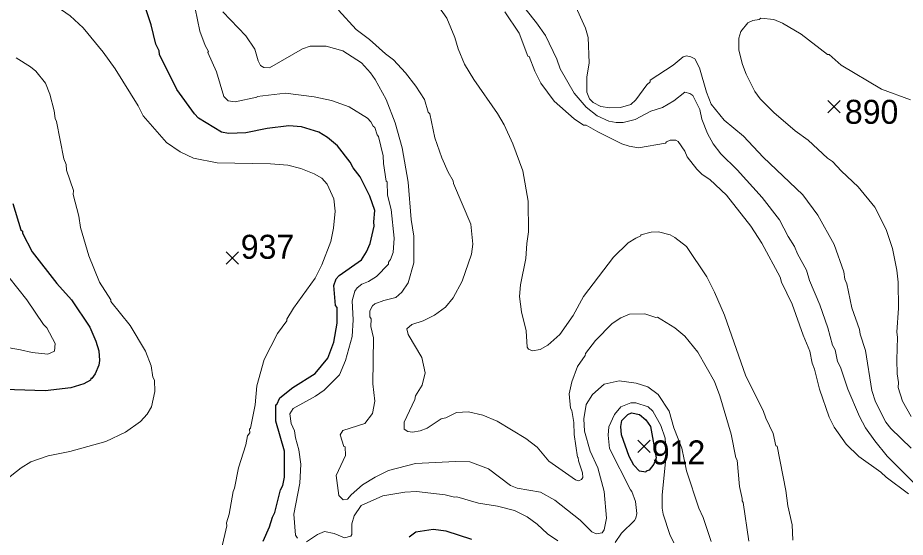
# Model space of a CAD drawing. Extents: x 265.7 to 292.1, y 7676.2 to 7704.2.
# Drawn here: x 279.917 to 282.881, y 7683.549 to 7685.284 of the extents above; entities that cross this region are included whole.
import ezdxf
from ezdxf.enums import TextEntityAlignment as Align

# ---------------------------------------------------------------- set-up
doc = ezdxf.new("R2010")
doc.units = 0
doc.header["$LTSCALE"] = 0.032
for name, color, linetype, lineweight in [('1', 7, 'Continuous', 25), ('2', 7, 'Continuous', 13), ('21', 7, 'Continuous', 25)]:
    doc.layers.add(name, color=color, linetype=linetype, lineweight=lineweight)
doc.layers.add('61', color=7, linetype='Continuous')

msp = doc.modelspace()

# ---------------------------------------------------------------- linework, layer by layer
at = {"layer": '1'}
for points in [[(280.4484, 7685.0448), (280.3902, 7685.1613), (280.3894, 7685.1741), (280.3782, 7685.1964), (280.3623, 7685.2603), (280.3431, 7685.3177), (280.3391, 7685.3497)], [(280.7365, 7683.5367), (280.758, 7683.5846), (280.7676, 7683.6165), (280.7756, 7683.6324), (280.7948, 7683.7074), (280.8019, 7683.7218), (280.8075, 7683.7505), (280.8075, 7683.8367), (280.7788, 7683.9373), (280.7788, 7683.9915), (280.782, 7683.9923), (280.7916, 7684.0155), (280.8355, 7684.049), (280.9097, 7684.0968), (280.9528, 7684.1471), (280.9719, 7684.2006), (280.9831, 7684.2644), (280.9831, 7684.3171), (280.9783, 7684.3235), (280.9719, 7684.3905), (280.9807, 7684.412), (280.9902, 7684.424), (281.0653, 7684.4759), (281.082, 7684.5022), (281.094, 7684.5309), (281.1076, 7684.5884), (281.106, 7684.6028), (281.1091, 7684.6403), (281.0932, 7684.6889), (281.0605, 7684.7528), (281.0373, 7684.7831), (281.027, 7684.8023), (280.9847, 7684.8565), (280.9512, 7684.8844), (280.9224, 7684.902), (280.865, 7684.9195), (280.8219, 7684.9235), (280.7501, 7684.9148), (280.6783, 7684.8996), (280.6208, 7684.898), (280.5977, 7684.902), (280.5211, 7684.9491), (280.5067, 7684.9634), (280.4484, 7685.0448)], [(279.901, 7684.6634), (279.9274, 7684.5756), (279.9329, 7684.5716), (279.9329, 7684.5652), (279.9649, 7684.5022), (280.0479, 7684.3969), (280.0965, 7684.3426), (280.1572, 7684.2509), (280.1779, 7684.2038), (280.1875, 7684.1719), (280.1899, 7684.1399), (280.1875, 7684.124), (280.1755, 7684.0953), (280.1644, 7684.0801), (280.1612, 7684.0801), (280.1596, 7684.0745), (280.1372, 7684.0617), (280.0942, 7684.0482), (280.008, 7684.0386), (279.7351, 7684.0474)], [(281.4331, 7683.5415), (281.347, 7683.5702), (281.3039, 7683.575), (281.2464, 7683.5662), (281.2241, 7683.5494)]]:
    msp.add_lwpolyline(points, dxfattribs=at)
msp.add_lwpolyline([(282.0299, 7683.9188), (282.0489, 7683.8144), (282.041, 7683.7938), (282.0252, 7683.7737), (282.0156, 7683.7705), (282.014, 7683.7665), (281.9933, 7683.7705), (281.9741, 7683.7904), (281.9582, 7683.8192), (281.9334, 7683.891), (281.931, 7683.9197), (281.9342, 7683.9397), (281.9542, 7683.9588), (281.9662, 7683.9652), (281.9933, 7683.9588), (282.014, 7683.9412)], close=True, dxfattribs=at)
at = {"layer": '2'}
for points in [[(280.2019, 7685.1693), (280.1356, 7685.2507), (280.0918, 7685.2906), (280.0167, 7685.3425), (279.9824, 7685.3616), (279.8931, 7685.4031), (279.7925, 7685.443)], [(281.5456, 7685.3983), (281.6494, 7685.2675), (281.6789, 7685.2252), (281.7172, 7685.1454), (281.7284, 7685.1135), (281.7747, 7685.0321), (281.8145, 7684.9858), (281.8513, 7684.9562), (281.8912, 7684.9387), (281.9151, 7684.9339), (281.939, 7684.9339), (281.9789, 7684.9443), (282.0308, 7684.9722), (282.0699, 7684.9842), (282.1082, 7685.0065), (282.1449, 7685.0352), (282.1609, 7685.0313), (282.1712, 7685.0241), (282.1944, 7684.9778), (282.2016, 7684.9459), (282.2199, 7684.898), (282.2391, 7684.8629), (282.2646, 7684.8302), (282.3197, 7684.7759), (282.4026, 7684.6842), (282.4601, 7684.6099), (282.4896, 7684.5533), (282.5112, 7684.5198), (282.5207, 7684.4958), (282.5511, 7684.4408), (282.5606, 7684.4065), (282.595, 7684.3259), (282.6221, 7684.2485), (282.638, 7684.191), (282.646, 7684.1751), (282.6548, 7684.1368), (282.6644, 7684.1176), (282.6891, 7684.0442), (282.7274, 7683.9532), (282.7482, 7683.9149), (282.7785, 7683.871), (282.82, 7683.82), (282.9086, 7683.7322)], [(281.7747, 7685.3329), (281.813, 7685.2499), (281.8217, 7685.2188), (281.8249, 7685.1342), (281.8177, 7685.0863), (281.8177, 7685.0353), (281.8265, 7685.0137), (281.8385, 7685.0009), (281.864, 7684.9882), (281.8944, 7684.9834), (281.9295, 7684.9842), (281.9638, 7684.9946), (281.9805, 7685.0097), (282.0172, 7685.06), (282.0284, 7685.0704), (282.0292, 7685.076), (282.105, 7685.1262), (282.1393, 7685.1533), (282.1505, 7685.1565), (282.1641, 7685.1541), (282.1776, 7685.147), (282.1936, 7685.1174), (282.2167, 7685.0353), (282.2327, 7684.9954), (282.2758, 7684.9419), (282.3404, 7684.8884), (282.4058, 7684.8182), (282.5383, 7684.6929), (282.5886, 7684.6251), (282.6436, 7684.527), (282.6756, 7684.4352), (282.6787, 7684.4113), (282.6859, 7684.3953), (282.7019, 7684.3155), (282.7274, 7684.2437), (282.7298, 7684.2277), (282.7474, 7684.1735), (282.7689, 7684.0394), (282.7809, 7684.0011), (282.8152, 7683.9341), (282.8327, 7683.9125), (282.8998, 7683.8471)], [(280.8514, 7683.5463), (280.845, 7683.5566), (280.8394, 7683.6261), (280.8586, 7683.7298), (280.8618, 7683.7936), (280.8554, 7683.8415), (280.8442, 7683.8814), (280.841, 7683.9053), (280.8299, 7683.9293), (280.8259, 7683.9612), (280.8371, 7683.9795), (280.9113, 7684.0202), (280.94, 7684.041), (280.9911, 7684.0913), (281.0118, 7684.1399), (281.0333, 7684.2197), (281.0373, 7684.2756), (281.0341, 7684.3394), (281.0421, 7684.3714), (281.0501, 7684.3825), (281.0661, 7684.3945), (281.0884, 7684.4033), (281.1147, 7684.42), (281.1554, 7684.4615), (281.1554, 7684.4679), (281.1618, 7684.4767), (281.1706, 7684.5006), (281.1738, 7684.5485), (281.1642, 7684.6443), (281.1522, 7684.6921), (281.1506, 7684.7368), (281.1475, 7684.7384), (281.1379, 7684.7975), (281.1371, 7684.823), (281.1219, 7684.8876), (281.1171, 7684.8932), (281.1092, 7684.918), (281.1036, 7684.9219), (281.0964, 7684.9371), (281.0852, 7684.9491), (281.0238, 7684.9866), (280.9647, 7685.0081), (280.9065, 7685.0201), (280.8107, 7685.0321), (280.7166, 7685.0217), (280.715, 7685.0185), (280.6432, 7685.0033), (280.6192, 7685.0065), (280.6048, 7685.0217), (280.5809, 7685.1039), (280.5522, 7685.1677), (280.5538, 7685.1717), (280.5426, 7685.1917), (280.525, 7685.2395), (280.5091, 7685.3153)], [(281.8154, 7683.9931), (281.8074, 7683.9452), (281.8098, 7683.9037), (281.8281, 7683.8367), (281.8544, 7683.7809), (281.8752, 7683.7027), (281.8832, 7683.6133), (281.8752, 7683.5742), (281.868, 7683.5638), (281.8481, 7683.5606), (281.8337, 7683.567), (281.7946, 7683.6061), (281.71, 7683.6731), (281.6629, 7683.6995), (281.5847, 7683.7138), (281.5624, 7683.7218), (281.489, 7683.7777), (281.4267, 7683.8008), (281.3789, 7683.8024), (281.2448, 7683.7952), (281.1554, 7683.7721), (281.1108, 7683.7505), (281.0677, 7683.7242), (281.0302, 7683.6915), (281.0182, 7683.6763), (281.0038, 7683.6747), (280.9887, 7683.6891), (280.9799, 7683.7553), (281.0118, 7683.8224), (281.0102, 7683.8511), (281.0062, 7683.8527), (280.9934, 7683.8918), (281.0022, 7683.9061), (281.0756, 7683.9293), (281.102, 7683.9628), (281.1092, 7684.0035), (281.1028, 7684.0617), (281.1044, 7684.215), (281.0964, 7684.2533), (281.0972, 7684.2788), (281.0932, 7684.2852), (281.0932, 7684.3051), (281.1012, 7684.3219), (281.1091, 7684.3291), (281.1395, 7684.3402), (281.1794, 7684.3498), (281.1993, 7684.3674), (281.2209, 7684.3985), (281.24, 7684.4655), (281.24, 7684.5549), (281.2304, 7684.6107), (281.2209, 7684.7352), (281.2009, 7684.8501), (281.1778, 7684.9331), (281.1475, 7685.0113), (281.1107, 7685.0783), (281.0948, 7685.1007), (281.0645, 7685.1334), (281.003, 7685.1741), (280.9464, 7685.1893), (280.8937, 7685.1893), (280.8682, 7685.1805), (280.7581, 7685.1166), (280.7389, 7685.1182), (280.7277, 7685.1246), (280.7198, 7685.1406), (280.7086, 7685.1789), (280.6783, 7685.2236), (280.6017, 7685.3034)], [(281.7675, 7683.9724), (281.7739, 7683.9325), (281.7755, 7683.8926), (281.7858, 7683.8168), (281.7882, 7683.816), (281.789, 7683.8048), (281.8026, 7683.7649), (281.8034, 7683.7489), (281.7994, 7683.7426), (281.789, 7683.7378), (281.7794, 7683.741), (281.6901, 7683.8032), (281.651, 7683.8503), (281.6135, 7683.879), (281.5177, 7683.9373), (281.4698, 7683.9572), (281.422, 7683.9684), (281.3821, 7683.966), (281.3469, 7683.9484), (281.331, 7683.9452), (281.2839, 7683.9141), (281.2608, 7683.9045), (281.2352, 7683.9005), (281.2201, 7683.9029), (281.2073, 7683.9109), (281.2073, 7683.9333), (281.2432, 7684.0091), (281.2456, 7684.0218), (281.2671, 7684.057), (281.2775, 7684.0985), (281.2664, 7684.1495), (281.2209, 7684.2261), (281.2161, 7684.2453), (281.2328, 7684.2604), (281.2703, 7684.2716), (281.3087, 7684.2915), (281.3454, 7684.3179), (281.3709, 7684.349), (281.4012, 7684.4049), (281.4323, 7684.4942), (281.4363, 7684.5278), (281.4299, 7684.5948), (281.3725, 7684.7304), (281.3709, 7684.74), (281.3541, 7684.7687), (281.3326, 7684.8166), (281.3102, 7684.8836), (281.2935, 7684.9634), (281.2879, 7684.969), (281.2751, 7685.0113), (281.2464, 7685.056), (281.2113, 7685.1007), (281.1722, 7685.1438), (281.1451, 7685.1637), (281.0916, 7685.2116), (281.0469, 7685.2451), (280.9879, 7685.309)], [(282.5056, 7683.5399), (282.5024, 7683.5909), (282.488, 7683.6548), (282.4816, 7683.7059), (282.4529, 7683.8535), (282.4489, 7683.8551), (282.4394, 7683.8958), (282.4146, 7683.9468), (282.4058, 7683.9724), (282.3484, 7684.0873), (282.2766, 7684.2916), (282.2439, 7684.3682), (282.2175, 7684.4192), (282.1497, 7684.5198), (282.1114, 7684.5509), (282.0954, 7684.5589), (282.0571, 7684.5692), (282.0316, 7684.5684), (281.9981, 7684.5589), (281.9981, 7684.5557), (281.9805, 7684.5485), (281.955, 7684.5325), (281.9063, 7684.4847), (281.8066, 7684.3538), (281.7715, 7684.29), (281.7268, 7684.2261), (281.6869, 7684.191), (281.6613, 7684.1766), (281.6358, 7684.1719), (281.623, 7684.1774), (281.6183, 7684.1838), (281.6151, 7684.2389), (281.5991, 7684.3027), (281.5927, 7684.3538), (281.5959, 7684.3921), (281.6135, 7684.4799), (281.6167, 7684.5309), (281.623, 7684.5692), (281.6214, 7684.6714), (281.6031, 7684.7735), (281.5704, 7684.8629), (281.5416, 7684.9267), (281.5193, 7684.965), (281.4403, 7685.0783), (281.4092, 7685.1294), (281.3876, 7685.1805), (281.3765, 7685.2188), (281.3493, 7685.2826), (281.323, 7685.3209)], [(281.544, 7685.3042), (281.5911, 7685.2332)], [(282.8982, 7685.0097), (282.8008, 7685.0456), (282.6668, 7685.1262), (282.6269, 7685.1613), (282.6205, 7685.1613), (282.5335, 7685.2292), (282.4705, 7685.2659), (282.4418, 7685.2778), (282.3987, 7685.2826), (282.3923, 7685.2786), (282.3715, 7685.2754), (282.3548, 7685.2667), (282.3316, 7685.2379), (282.3244, 7685.2156), (282.3252, 7685.1757), (282.3372, 7685.1278), (282.3492, 7685.0959), (282.3779, 7685.0384), (282.3955, 7685.0137), (282.4418, 7684.9682), (282.5128, 7684.9068), (282.5559, 7684.8749), (282.6205, 7684.8158), (282.6381, 7684.8046), (282.6676, 7684.7719), (282.7234, 7684.7201), (282.7785, 7684.6522), (282.8168, 7684.5772), (282.8383, 7684.5134), (282.8527, 7684.4416), (282.8567, 7684.4017), (282.8583, 7684.3139), (282.8527, 7684.2341), (282.8551, 7684.2181), (282.8519, 7684.1415), (282.8535, 7684.0953), (282.8583, 7684.0665), (282.8567, 7684.049), (282.8711, 7684.0043), (282.8998, 7683.9532)], [(281.5911, 7685.2332), (281.6206, 7685.1557), (281.6246, 7685.155), (281.6438, 7685.1055), (281.6637, 7685.0656), (281.7084, 7685.0057), (281.7755, 7684.9467)], [(279.9122, 7685.1502), (279.9594, 7685.1205), (279.9773, 7685.1057), (280.0096, 7685.0656), (280.0239, 7685.0289), (280.0391, 7684.973), (280.0415, 7684.9475), (280.0463, 7684.9379), (280.071, 7684.8134), (280.0782, 7684.7943), (280.0798, 7684.7751), (280.1037, 7684.7073), (280.1021, 7684.6945), (280.1213, 7684.6219), (280.1269, 7684.5836), (280.154, 7684.4895), (280.1899, 7684.4017), (280.2282, 7684.3426), (280.2282, 7684.3362), (280.2928, 7684.2564), (280.3439, 7684.1703), (280.3623, 7684.1224), (280.3686, 7684.0841), (280.3734, 7684.0745), (280.375, 7684.0362), (280.3639, 7683.9851), (280.3495, 7683.9604), (280.3264, 7683.9365), (280.2769, 7683.8998), (280.2107, 7683.8694), (280.091, 7683.8359), (280.0191, 7683.8216), (279.9609, 7683.8016), (279.9282, 7683.7809), (279.838, 7683.7114)], [(280.5969, 7683.5112), (280.6152, 7683.5878), (280.6144, 7683.5973), (280.6232, 7683.6261), (280.636, 7683.7027), (280.6408, 7683.7138), (280.6543, 7683.7809), (280.6783, 7683.8575), (280.6846, 7683.8878), (280.6918, 7683.8982), (280.691, 7683.9101), (280.6942, 7683.9133), (280.7094, 7683.9915), (280.7158, 7684.0554), (280.7397, 7684.1431), (280.7844, 7684.2293), (280.8155, 7684.2716), (280.8155, 7684.278), (280.8378, 7684.3139), (280.9097, 7684.4144), (280.9328, 7684.4591), (280.9623, 7684.5373), (280.9711, 7684.582), (280.9767, 7684.6379), (280.9719, 7684.6794), (280.9504, 7684.7288), (280.932, 7684.748), (280.9065, 7684.7631), (280.8618, 7684.7807), (280.8187, 7684.7919), (280.7612, 7684.7967), (280.5825, 7684.7999), (280.5043, 7684.815), (280.4596, 7684.8366), (280.4133, 7684.8677), (280.3359, 7684.9571), (280.3192, 7684.9906), (280.2418, 7685.1135), (280.2019, 7685.1693)], [(281.7755, 7684.9467), (281.8066, 7684.9259), (281.8146, 7684.9259), (281.8545, 7684.9028), (281.9343, 7684.8637), (281.9582, 7684.8557), (281.9901, 7684.8501), (282.0795, 7684.8653), (282.0835, 7684.8701), (282.0954, 7684.8749), (282.1146, 7684.8749), (282.1226, 7684.8709), (282.1449, 7684.839), (282.1521, 7684.8198), (282.1848, 7684.7783), (282.2024, 7684.7608), (282.2279, 7684.744), (282.2838, 7684.6921), (282.3651, 7684.5884), (282.4011, 7684.5317), (282.4625, 7684.4176), (282.4673, 7684.4017), (282.5024, 7684.3283), (282.5391, 7684.2245), (282.5614, 7684.1711), (282.5694, 7684.1304), (282.5774, 7684.1112), (282.5942, 7684.0442), (282.6261, 7683.95), (282.6428, 7683.9165), (282.6835, 7683.8599), (282.7258, 7683.8192), (282.7992, 7683.7665), (282.8168, 7683.7497), (282.891, 7683.6939)], [(279.8867, 7684.4176), (279.9473, 7684.3426), (280.0032, 7684.2604), (280.0143, 7684.2493), (280.0415, 7684.1966), (280.0399, 7684.1711), (280.0175, 7684.1607), (279.9649, 7684.1663), (279.9266, 7684.1758), (279.8181, 7684.1942)], [(282.358, 7683.5367), (282.3396, 7683.6659), (282.3356, 7683.6707), (282.3364, 7683.6787), (282.3268, 7683.7186), (282.3189, 7683.8064), (282.3149, 7683.8144), (282.2989, 7683.8942), (282.2614, 7684.0218), (282.2431, 7684.0697), (282.188, 7684.1679), (282.1441, 7684.2213), (282.1106, 7684.2485), (282.0531, 7684.2844), (282.0476, 7684.2836), (282.0109, 7684.2955), (281.9598, 7684.2939), (281.9311, 7684.282), (281.9023, 7684.2628), (281.8465, 7684.2062), (281.813, 7684.1631)], [(281.813, 7684.1631), (281.8122, 7684.1567), (281.7858, 7684.12), (281.7667, 7684.0681), (281.7587, 7684.0282), (281.7627, 7683.9804), (281.7675, 7683.9724)], [(282.0555, 7684.0266), (282.0204, 7684.0522), (281.9821, 7684.0641), (281.9247, 7684.0713), (281.8752, 7684.0609), (281.8361, 7684.0266), (281.8154, 7683.9931)], [(282.2327, 7683.5351), (282.2056, 7683.6157), (282.1912, 7683.6468), (282.1505, 7683.7713), (282.1342, 7683.8471), (282.1079, 7683.9149), (282.0922, 7683.9708), (282.0555, 7684.0266)], [(282.1074, 7683.5303), (282.0946, 7683.559), (282.0723, 7683.6261), (282.0683, 7683.6468), (282.0691, 7683.6915), (282.0817, 7683.8233), (282.0789, 7683.8804), (282.0643, 7683.9229), (282.0372, 7683.9708), (282.022, 7683.9851), (281.9805, 7683.9979), (281.9646, 7683.9979), (281.9311, 7683.9851), (281.9095, 7683.9596), (281.8912, 7683.9181), (281.888, 7683.8902), (281.8928, 7683.8463)], [(281.8928, 7683.8463), (281.963, 7683.7074), (281.9678, 7683.7027), (281.9797, 7683.6691), (281.9837, 7683.6292), (281.9813, 7683.6133), (281.9765, 7683.6053)], [(281.7204, 7683.5375), (281.6861, 7683.5614), (281.651, 7683.5933), (281.6175, 7683.6181), (281.5752, 7683.6388), (281.5193, 7683.6532), (281.4555, 7683.6636), (281.3837, 7683.6843), (281.3757, 7683.6835), (281.3438, 7683.6915), (281.248, 7683.7019), (281.2097, 7683.7003), (281.1363, 7683.6883), (281.0637, 7683.6556), (281.0405, 7683.6205), (281.0325, 7683.5941), (281.0325, 7683.5582), (281.0294, 7683.5534), (281.0086, 7683.547), (280.9735, 7683.5622), (280.9416, 7683.5686), (280.9176, 7683.5582), (280.8809, 7683.5343)], [(281.9765, 7683.6053), (281.9327, 7683.563), (281.9119, 7683.5319)]]:
    msp.add_lwpolyline(points, dxfattribs=at)
at = {"layer": '21'}
for p, q in [((282.6225, 7685.0084), (282.6637, 7684.9672)), ((282.6637, 7685.0084), (282.6225, 7684.9672)), ((280.6127, 7684.502), (280.6539, 7684.4608)), ((280.6539, 7684.502), (280.6127, 7684.4608)), ((281.9873, 7683.8732), (282.0285, 7683.832)), ((282.0285, 7683.8732), (281.9873, 7683.832))]:
    msp.add_line(p, q, dxfattribs=at)

# ---------------------------------------------------------------- texts
at = {"layer": '61'}
for s, p in [('890', (282.7681, 7684.9301)), ('937', (280.7509, 7684.4794)), ('912', (282.1234, 7683.7928))]:
    msp.add_text(s, height=0.08, dxfattribs=at).set_placement(p, align=Align.CENTER)

doc.saveas('drawing.dxf')
